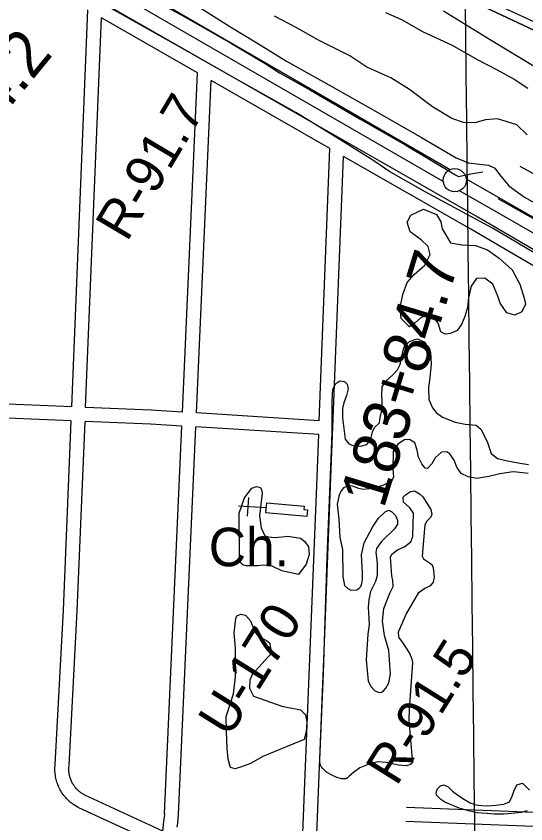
# Model space of a CAD drawing. Extents: x 3677843 to 3715951, y 511991 to 537744.
# Drawn here: x 3696854 to 3697951, y 526105 to 527844 of the extents above; entities that cross this region are included whole.
import ezdxf

# ---------------------------------------------------------------- set-up
doc = ezdxf.new("R2010")
doc.units = 0
for name, color, linetype in [('V-BLDG-OTLN', 7, 'Continuous'), ('V-FLOD-BASE', 7, 'Continuous'), ('V-GRID-MAJR', 7, 'Continuous'), ('V-LEVE-TOET', 7, 'Continuous'), ('V-RIVR-EDGE', 7, 'Continuous'), ('V-RIVR-RANG-IDEN', 7, 'Continuous'), ('V-ROAD-CNTR', 7, 'Continuous'), ('V-RRAP-FSHR', 7, 'Continuous'), ('V-SITE-OTLN', 7, 'Continuous'), ('V-SITE-OTLN-IDEN', 7, 'Continuous'), ('V-SITE-VEGE', 7, 'Continuous'), ('V-SURV-IDEN', 7, 'Continuous'), ('V-SURV-LINE', 7, 'Continuous'), ('V-TOPO-DPTH', 7, 'Continuous'), ('V-TOPO-MINR', 7, 'Continuous'), ('V-TOPO-WATR', 7, 'Continuous')]:
    doc.layers.add(name, color=color, linetype=linetype)

msp = doc.modelspace()

# ---------------------------------------------------------------- linework, layer by layer
at = {"layer": 'V-BLDG-OTLN'}
msp.add_lwpolyline([(3697391.767, 526774.828), (3697393.702, 526796.174), (3697474.295, 526788.865), (3697473.6520000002, 526781.783), (3697481.125, 526781.103), (3697479.8310000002, 526766.837)], close=True, dxfattribs=at)
at = {"layer": 'V-FLOD-BASE'}
for points in [[(3696963.823, 528025.251), (3696995.319, 527977.979), (3697007.7260000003, 527960.311), (3697020.612, 527949.805), (3697093.644, 527909.203), (3697209.634, 527846.628), (3697317.511, 527785.012), (3697390.063, 527742.025), (3697421.088, 527721.965), (3697487.437, 527684.707), (3697596.268, 527621.18), (3697692.688, 527566.251), (3697799.608, 527502.247), (3697806.29, 527498.425), (3697832.5500000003, 527504.147), (3697858.807, 527508.436)], [(3697891.256, 527451.6140000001), (3698032.066, 527371.3690000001), (3698147.577, 527303.067), (3698260.705, 527239.5380000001), (3698358.079, 527181.2660000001), (3698376.693, 527172.6680000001), (3698394.8340000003, 527169.797)]]:
    msp.add_lwpolyline(points, dxfattribs=at)
at = {"layer": 'V-GRID-MAJR'}
msp.add_spline([(3697869.728154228, 523644.39091797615), (3697800.0870000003, 529704.966), (3697730.4450000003, 535765.552), (3697730.4050000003, 535769.005)], degree=3, dxfattribs=at)
at = {"layer": 'V-LEVE-TOET'}
for points in [[(3698472.529, 527041.836), (3698361.237, 527107.313), (3698311.46, 527134.176), (3698275.108, 527154.884), (3698248.265, 527171.1140000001), (3698233.724, 527180.627), (3698164.377, 527221.48), (3698039.1010000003, 527292.554), (3697879.1520000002, 527387.692), (3697734.301, 527465.487), (3697656.563, 527510.259), (3697628.041, 527529.285), (3697610.704, 527541.036), (3697553.1, 527576.851), (3697456.349, 527636.172), (3697315.413, 527715.083), (3697199.646, 527781.68), (3697055.356, 527862.2710000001), (3697004.461, 527890.255), (3696967.552, 527915.435), (3696950.218, 527936.136)], [(3697236.031, 527871.167), (3697314.328, 527821.362), (3697371.93, 527786.106), (3697436.245, 527746.932), (3697533.556, 527692.086), (3697627.514, 527639.477), (3697726.504, 527582.954), (3697801.4450000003, 527538.742), (3697827.733, 527528.107), (3697851.7830000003, 527525.303), (3697870.8000000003, 527523.061), (3697884.782, 527516.902), (3697894.848, 527502.917), (3697914.419, 527478.3), (3697948.532, 527454.238), (3698041.929, 527401.0700000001)]]:
    msp.add_lwpolyline(points, dxfattribs=at)
at = {"layer": 'V-RIVR-EDGE'}
msp.add_lwpolyline([(3697774.287742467, 527855.332599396), (3697876.7871042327, 527792.0448515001), (3698092.5827345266, 527661.8406982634)], dxfattribs=at)
at = {"layer": 'V-ROAD-CNTR'}
for points in [[(3697847.86726536, 527411.081151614), (3697000.5939599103, 527896.364181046), (3696969.710021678, 527916.9121399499), (3696954.7250516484, 527929.4341149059), (3696929.2361026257, 527958.6060565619), (3696908.0561449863, 527985.235003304)], [(3696973.8140134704, 527002.59896858), (3697008.712943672, 527857.1412594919)], [(3697003.78895352, 527001.3769710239), (3697038.051884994, 527840.3372930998)], [(3697244.6574717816, 527722.0025297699), (3697038.051884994, 527840.3372930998)], [(3697212.247536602, 526991.3829910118), (3697244.655471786, 527722.0025297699)], [(3697242.192476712, 526989.4979947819), (3697273.941413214, 527705.228563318)], [(3697529.4889021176, 527558.86285605), (3697273.941413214, 527705.2295633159)], [(3697506.5909479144, 526972.8560280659), (3697529.48790212, 527558.861856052)], [(3697418.4121242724, 524147.15067948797), (3697430.934099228, 524455.6500624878), (3697472.191016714, 525398.1691774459), (3697491.9039772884, 525848.1442774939), (3697505.15795078, 526174.039625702), (3697518.02292505, 526495.2079833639), (3697530.41290027, 526814.1413454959), (3697558.853843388, 527542.0428896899)], [(3697832.9572951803, 527385.0492036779), (3697558.853843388, 527542.043889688)], [(3700025.079910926, 525999.309975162), (3699637.8166854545, 526223.06552765), (3699515.020931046, 526299.84537409), (3699487.6339858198, 526318.9453358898), (3699465.044031, 526340.9852918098), (3699441.2280786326, 526369.2072353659), (3699126.022709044, 526649.688674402), (3698935.528090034, 526775.5434226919), (3698552.726855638, 526999.5039747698), (3697847.976265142, 527411.0181517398)], [(3698024.977911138, 527272.9244279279), (3697832.848295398, 527385.112203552)], [(3696973.8140134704, 527002.59896858), (3696767.0014270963, 527011.025951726)], [(3697212.247536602, 526991.3839910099), (3697144.6486718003, 526995.6389824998), (3697003.78895352, 527001.3779710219)], [(3696972.590015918, 526972.6240285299), (3696765.773429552, 526981.0510116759)], [(3697506.5919479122, 526972.857028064), (3697242.1934767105, 526989.4989947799)], [(3696938.233084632, 526232.489508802), (3696955.9440492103, 526565.0548436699), (3696972.58901592, 526972.6240285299)], [(3696968.1910247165, 526230.8935119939), (3696985.911989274, 526563.6448464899), (3697002.56395597, 526971.4020309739)], [(3697210.9175392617, 526961.408050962), (3697143.094674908, 526965.677042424), (3697002.564955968, 526971.403030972)], [(3697173.8776133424, 526126.383721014), (3697210.9175392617, 526961.408050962)], [(3697203.847553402, 526125.0537236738), (3697240.8634793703, 526959.5230547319)], [(3697505.4199502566, 526942.8720880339), (3697240.8634793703, 526959.5230547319)], [(3697388.374184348, 524146.80568017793), (3697400.960159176, 524456.9140599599), (3697442.219076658, 525399.4811748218), (3697461.9300372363, 525849.410274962), (3697475.182010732, 526175.249623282), (3697488.0469850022, 526496.389981), (3697500.434960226, 526815.3093431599), (3697505.4199502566, 526942.8710880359)], [(3696988.8419834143, 526139.962693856), (3696986.414988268, 526141.222691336), (3696983.817993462, 526142.6786884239), (3696981.2699985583, 526144.218685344), (3696978.7760035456, 526145.8356821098), (3696976.331008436, 526147.5346787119), (3696973.9440132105, 526149.3096751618), (3696971.615017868, 526151.16067146), (3696969.3450224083, 526153.0856676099), (3696967.137026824, 526155.084663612), (3696964.998031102, 526157.1496594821), (3696962.92403525, 526159.2836552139), (3696960.920039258, 526161.482650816), (3696958.987043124, 526163.7456462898), (3696957.1280468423, 526166.0696416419), (3696955.34405041, 526168.4516368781), (3696953.6380538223, 526170.8906319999), (3696952.011057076, 526173.3796270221), (3696950.4650601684, 526175.921621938), (3696949.000063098, 526178.5116167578), (3696947.61906586, 526181.1496114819), (3696946.323068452, 526183.8286061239), (3696945.116070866, 526186.546600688), (3696943.9950731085, 526189.3015951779), (3696942.9610751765, 526192.097589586), (3696942.021077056, 526194.917583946), (3696941.170078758, 526197.7675782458), (3696940.411080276, 526200.64557249), (3696939.74408161, 526203.5455666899), (3696939.171082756, 526206.466560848), (3696938.692083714, 526209.4005549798), (3696938.307084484, 526212.3525490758), (3696938.017085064, 526215.3165431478), (3696937.822085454, 526218.2865372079), (3696937.7230856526, 526221.257531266), (3696937.71908566, 526224.234525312), (3696937.810085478, 526227.2085193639), (3696937.996085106, 526230.176513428), (3696938.2680845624, 526233.037507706), (3696938.3080844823, 526233.3865070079)], [(3697002.6699557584, 526166.5846406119), (3697000.66895976, 526167.6246385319), (3696998.9139632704, 526168.608636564), (3696997.191966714, 526169.6486344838), (3696995.499970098, 526170.7456322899), (3696993.846973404, 526171.894629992), (3696992.231976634, 526173.09562759), (3696990.6549797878, 526174.3486250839), (3696989.1189828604, 526175.651622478), (3696987.62898584, 526177.0006197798), (3696986.177988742, 526178.401616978), (3696984.77399155, 526179.84561409), (3696983.4179942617, 526181.3346111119), (3696982.110996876, 526182.8636080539), (3696980.8539993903, 526184.4356049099), (3696979.6460018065, 526186.047601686), (3696978.492004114, 526187.696598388), (3696977.391006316, 526189.3835950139), (3696976.3430084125, 526191.1055915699), (3696975.352010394, 526192.8575880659), (3696974.4190122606, 526194.639584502), (3696973.5430140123, 526196.4525808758), (3696972.72401565, 526198.2945771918), (3696971.9650171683, 526200.159573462), (3696971.2690185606, 526202.0435696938), (3696970.6310198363, 526203.9575658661), (3696970.0540209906, 526205.887562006), (3696969.541022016, 526207.8335581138), (3696969.090022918, 526209.79555419), (3696968.703023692, 526211.7705502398), (3696968.378024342, 526213.7605462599), (3696968.117024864, 526215.7565422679), (3696967.921025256, 526217.7585382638), (3696967.7900255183, 526219.7665342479), (3696967.723025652, 526221.7815302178), (3696967.7190256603, 526223.794526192), (3696967.782025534, 526225.806522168), (3696967.908025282, 526227.8185181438), (3696968.1080248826, 526229.9235139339), (3696968.1160248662, 526229.996513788)], [(3697170.1076208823, 526089.4747948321), (3697002.031957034, 526166.8976399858)], [(3697165.8526293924, 526058.4058569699), (3696989.479982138, 526139.6496944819)], [(3697694.130572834, 526140.8646920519), (3697968.286024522, 526130.222713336)], [(3697170.1076208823, 526089.4747948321), (3697172.3246164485, 526110.2007533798), (3697173.2266146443, 526119.367735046), (3697173.92361325, 526127.0697196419)], [(3697201.1615587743, 526097.7287783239), (3697202.16855676, 526107.1367595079), (3697203.094554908, 526116.547740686), (3697203.801553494, 526124.3677250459)], [(3697692.966575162, 526110.886752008), (3697966.9930271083, 526100.2507732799)]]:
    msp.add_lwpolyline(points, dxfattribs=at)
at = {"layer": 'V-RRAP-FSHR'}
msp.add_lwpolyline([(3697938.220454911, 527521.049574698), (3698516.60432745, 527203.8594304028), (3699111.751080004, 526846.0041980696), (3699438.6651283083, 526626.4114938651), (3699664.989608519, 526398.686181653), (3700251.7538970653, 526032.6983413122), (3700696.02039348, 525748.040677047), (3701056.4622498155, 525536.58262885)], dxfattribs=at)
at = {"layer": 'V-SITE-OTLN'}
for p, q in [((3697354.0750957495, 526807.5817980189), (3697351.6680134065, 526767.6537777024)), ((3697392.7985759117, 526785.2107505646), (3697332.907544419, 526788.821329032))]:
    msp.add_line(p, q, dxfattribs=at)
at = {"layer": 'V-SITE-VEGE'}
for points in [[(3697954.299, 527588.5), (3697931.718, 527609.963), (3697890.504, 527622.962), (3697864.531, 527620.711), (3697841.381, 527614.508), (3697817.102, 527615.079), (3697792.259, 527623.554), (3697750.484, 527648.411), (3697700.808, 527685.6900000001), (3697660.727, 527711.112), (3697609.353, 527733.712), (3697572.659, 527758.566), (3697504.913, 527791.9), (3697455.798, 527820.1460000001), (3697410.6350000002, 527843.8740000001)], [(3697648.912, 527851.707), (3697683.347, 527837.017), (3697730.205, 527810.4670000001), (3697792.872, 527781.086), (3697846.501, 527750.581), (3697889.406, 527727.984), (3697926.102, 527708.21), (3697955.4560000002, 527689.004)], [(3697699.651, 526329.148), (3697706.069, 526251.64), (3697707.913, 526239.901), (3697705.596, 526235.184), (3697703.264, 526232.819), (3697693.296, 526229.81), (3697676.832, 526231.459), (3697650.941, 526237.152), (3697632.716, 526238.789), (3697615.126, 526233.966), (3697594.032, 526225.591), (3697580.003, 526215.507), (3697571.2430000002, 526207.806), (3697567.475, 526203.762), (3697563.484, 526201.73), (3697555.472, 526201.675), (3697544.236, 526204.8), (3697532.577, 526210.328), (3697522.12, 526216.263), (3697514.055, 526223.818), (3697510.42, 526228.6), (3697509.197, 526231.395), (3697507.958, 526236.593), (3697507.921, 526243.4230000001), (3697515.64, 526429.507), (3697523.8850000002, 526679.264), (3697532.389, 526890.655), (3697534.1210000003, 526947.685), (3697534.734, 527012.699), (3697535.149, 527029.22), (3697536.1350000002, 527040.953), (3697542.444, 527052.7170000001), (3697550.931, 527058.64), (3697561.063, 527057.645), (3697566.433, 527051.8200000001), (3697568.634, 527041.711), (3697565.003, 527027.297), (3697559.789, 527011.276), (3697556.676, 526998.998), (3697556.8170000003, 526978.7490000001), (3697562.4620000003, 526933.497), (3697570.5270000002, 526923.427), (3697581.748, 526918.71), (3697595.606, 526918.274), (3697608.904, 526921.563), (3697617.883, 526933.349), (3697620.971, 526948.824), (3697625.169, 526958.446), (3697635.94, 526968.434), (3697637.805, 526979.851), (3697641.9420000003, 526997.9940000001), (3697641.83, 527013.979), (3697641.201, 527027.832), (3697642.139, 527045.955), (3697648.99, 527057.194), (3697665.4020000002, 527072.228), (3697674.923, 527082.419), (3697680.703, 527094.183), (3697684.815, 527115.525), (3697689.497, 527132.077), (3697700.6070000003, 527143.345), (3697717.086, 527149.321), (3697733.654, 527141.977), (3697746.065, 527120.213), (3697747.304, 527095.18), (3697744.312, 527065.853), (3697741.805, 527043.454), (3697742.514, 527018.4130000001), (3697750.097, 527000.35), (3697758.16, 526990.282), (3697772.0870000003, 526980.255), (3697799.335, 526969.787), (3697820.68, 526965.6730000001), (3697844.144, 526963.172), (3697855.395, 526954.192), (3697868.382, 526926.04), (3697876.541, 526902.1190000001), (3697890.469, 526891.56), (3697911.822, 526886.378), (3697934.7630000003, 526882.274), (3697957.169, 526878.703)], [(3697739.8200000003, 526869.724), (3697734.483, 526870.752), (3697727.489, 526880.296), (3697720.463, 526894.634), (3697717.161, 526909.531), (3697712.258, 526924.948), (3697701.017, 526932.331), (3697690.363, 526931.725), (3697676.04, 526922.567), (3697666.0270000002, 526906.51), (3697665.2260000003, 526868.671), (3697666.4080000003, 526852.16), (3697664.313, 526846.817), (3697661.147, 526842.531), (3697643.091, 526833.348), (3697621.823, 526826.804), (3697600.915, 526825.125)], [(3697956.235, 526859.513), (3697945.034, 526861.032), (3697923.71, 526862.482), (3697894.963, 526858.552), (3697871.556, 526853.06), (3697846.009, 526848.6190000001), (3697827.3340000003, 526852.216), (3697811.832, 526859.0380000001), (3697802.6780000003, 526872.829), (3697796.7120000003, 526887.706), (3697787.555, 526901.497), (3697781.133, 526905.714), (3697769.949, 526905.103), (3697756.176, 526893.284), (3697748.807, 526879.9130000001), (3697739.8200000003, 526869.724)], [(3697600.915, 526825.125), (3697591.592, 526827.208), (3697575.694, 526832.385), (3697565.126, 526831.136), (3697558.683, 526828.154), (3697552.279, 526819.884), (3697548.824, 526809.873), (3697545.414, 526793.395), (3697548.576, 526761.104), (3697550.614, 526721.754), (3697556.6720000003, 526695.9450000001), (3697557.075, 526637.782), (3697560.737, 526618.4180000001), (3697568.423, 526611.422), (3697574.326, 526607.939), (3697587.244, 526608.616), (3697592.508, 526612.178), (3697596.008, 526615.727), (3697598.312, 526622.207), (3697600.014, 526631.032), (3697599.324, 526645.716), (3697597.878, 526684.483), (3697603.575, 526709.786), (3697621.551, 526743.987), (3697633.755, 526762.876), (3697648.3510000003, 526776.4890000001), (3697656.551, 526780.073), (3697663.037, 526776.593), (3697670.727, 526769.008), (3697674.911, 526759.0480000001), (3697674.973, 526750.236), (3697668.579, 526740.205), (3697640.568, 526712.98), (3697629.511, 526697.629), (3697628.395, 526689.3960000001), (3697630.9, 526667.087), (3697631.092, 526639.474), (3697627.66, 526626.524), (3697616.643, 526605.297), (3697613.2460000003, 526587.059), (3697611.593, 526571.183), (3697614.202, 526534.188), (3697610.821, 526513.599), (3697607.681, 526458.351), (3697612.119, 526411.965), (3697618.079, 526399.669), (3697625.184, 526392.081), (3697634.613, 526388.035), (3697640.4820000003, 526388.6630000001), (3697644.574, 526391.629), (3697649.825, 526396.954), (3697656.207, 526408.748), (3697660.184, 526428.165), (3697656.309, 526478.079), (3697646.684, 526510.327), (3697642.94, 526541.4400000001), (3697645.69, 526568.484), (3697658.386, 526601.475), (3697665.335, 526615.625), (3697664.659, 526628.546), (3697662.824, 526639.107), (3697660.194, 526679.041), (3697663.086, 526685.525), (3697674.77, 526695.007), (3697690.5840000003, 526702.167), (3697704.026, 526712.2490000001), (3697708.06, 526723.442), (3697709.469, 526773.978), (3697701.75, 526785.674), (3697687.5700000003, 526797.327), (3697686.9020000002, 526808.485), (3697692.157, 526813.2220000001), (3697702.684, 526820.3470000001), (3697711.488, 526821.584), (3697722.103, 526815.782), (3697729.791, 526808.786), (3697747.017, 526781.879), (3697748.8540000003, 526771.316), (3697745.967, 526764.248), (3697738.381, 526756.556), (3697733.736, 526748.884), (3697728.3310000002, 526681.279), (3697730.723, 526675.422), (3697743.71, 526666.7), (3697749.614, 526662.628), (3697752.008, 526656.181), (3697753.911, 526636.219), (3697751.6350000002, 526625.039), (3697745.2290000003, 526617.357), (3697733.521, 526611.4), (3697719.486, 526601.901), (3697694.5270000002, 526558.25), (3697676.597, 526517.585), (3697677.25, 526508.189), (3697678.45, 526504.672), (3697685.5670000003, 526495.321), (3697701.597, 526471.345), (3697705.791, 526459.622), (3697707.603, 526452.585), (3697700.083, 526351.478), (3697699.651, 526329.148)], [(3697954.267, 526132.979), (3697940.973, 526129.155), (3697920.737, 526127.416), (3697903.6950000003, 526125.7), (3697883.977, 526126.093), (3697867.98, 526127.58), (3697846.656, 526129.03), (3697827.444, 526133.159), (3697807.687, 526138.883), (3697776.693, 526151.456), (3697768.126, 526157.258), (3697759.004, 526166.785), (3697757.898, 526172.106), (3697761.04, 526180.12), (3697767.387, 526187.093), (3697774.833, 526188.7440000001), (3697783.9220000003, 526184.5430000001), (3697793.58, 526175.02), (3697806.968, 526165.5210000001), (3697819.2830000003, 526157.082), (3697831.5870000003, 526150.2390000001), (3697843.341, 526146.059), (3697856.139, 526144.55), (3697868.93, 526144.105), (3697886.506, 526145.295), (3697903.548, 526147.012), (3697915.764, 526152.426), (3697921.542, 526164.723), (3697925.722, 526176.474), (3697932.029, 526188.774), (3697944.2600000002, 526192.5920000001), (3697958.754, 526177.238)]]:
    msp.add_lwpolyline(points, dxfattribs=at)
for points in [[(3697768.48, 527164.56), (3697762.279, 527182.616), (3697752.129, 527195.596), (3697737.4590000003, 527198.42), (3697725.611, 527195.039), (3697713.7600000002, 527184.324), (3697700.781, 527175.3), (3697682.7320000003, 527192.794), (3697680.484, 527216.491), (3697686.132, 527244.699), (3697695.731, 527270.649), (3697710.97, 527287.569), (3697734.1070000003, 527307.871), (3697745.397, 527330.9990000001), (3697740.89, 527347.926), (3697726.224, 527362.6), (3697702.535, 527379.533), (3697695.77, 527400.41), (3697703.673, 527415.639), (3697730.756, 527428.044), (3697758.963, 527416.7490000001), (3697768.5500000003, 527400.953), (3697770.8030000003, 527386.283), (3697788.845, 527355.813), (3697814.2320000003, 527351.854), (3697843.009, 527350.154), (3697868.392, 527341.12), (3697893.775, 527323.057), (3697921.9760000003, 527297.662), (3697938.329, 527267.192), (3697947.346, 527236.7220000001), (3697950.162, 527223.746), (3697942.259, 527207.386), (3697927.589, 527200.056), (3697910.1010000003, 527205.139), (3697896.003, 527226.017), (3697890.93, 527241.254), (3697880.217, 527267.208), (3697863.296, 527279.625), (3697845.241, 527279.066), (3697833.389, 527262.709), (3697827.741, 527237.322), (3697825.4760000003, 527216.448), (3697819.83, 527197.269), (3697813.055, 527179.779), (3697803.46, 527167.37), (3697788.788, 527160.606), (3697777.506, 527158.916)], [(3697461.753, 526641.669), (3697426.3310000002, 526649.957), (3697405.536, 526659.569), (3697387.2290000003, 526661.879), (3697373.822, 526660.566), (3697349.437, 526660.3960000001), (3697342.103, 526662.784), (3697338.429, 526665.197), (3697334.71, 526673.706), (3697334.011, 526773.693), (3697345.9760000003, 526806.701), (3697361.682, 526827.541), (3697371.412, 526831.267), (3697379.964, 526828.887), (3697382.436, 526824.027), (3697383.7060000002, 526816.72), (3697377.951, 526767.904), (3697381.787, 526742.322), (3697389.223, 526725.303), (3697396.557, 526722.9130000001), (3697412.417, 526721.805), (3697439.225, 526724.433), (3697466.0870000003, 526719.743), (3697475.8910000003, 526712.493), (3697483.284, 526701.571), (3697484.625, 526684.509), (3697478.6720000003, 526663.736)], [(3697473.988, 526286.906), (3697385.23, 526249.702), (3697358.505, 526234.883), (3697339.0470000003, 526227.43), (3697325.66, 526223.678), (3697315.889, 526226.05), (3697310.883, 526244.306), (3697308.282, 526267.456), (3697306.808, 526304.03), (3697306.5870000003, 526335.733), (3697310.166, 526346.733), (3697314.934, 526362.6190000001), (3697322.096, 526384.616), (3697326.718, 526421.233), (3697326.284, 526483.4180000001), (3697323.616, 526516.323), (3697327.06, 526546.834), (3697329.457, 526552.948), (3697337.968, 526556.667), (3697347.739, 526554.295), (3697358.798, 526542.177), (3697363.769, 526528.8), (3697367.494, 526519.0700000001), (3697374.879, 526509.366), (3697393.237, 526499.737), (3697400.598, 526493.693), (3697400.647, 526486.379), (3697404.399, 526472.988), (3697362.046, 526426.357), (3697357.254, 526414.128), (3697356.154, 526397.05), (3697364.807, 526380.037), (3697391.701, 526370.471), (3697425.93, 526358.515), (3697466.228, 526350.261), (3697477.2770000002, 526339.362), (3697479.829, 526323.527), (3697478.754, 526302.791)]]:
    msp.add_lwpolyline(points, close=True, dxfattribs=at)
at = {"layer": 'V-SURV-LINE'}
for points in [[(3697026.4984274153, 527954.7999564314), (3697788.5065170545, 527513.6011783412)], [(3697773.47298206, 527487.6398064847), (3697011.4641852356, 527928.8389940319)], [(3697823.0585507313, 527493.7099047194), (3699005.265645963, 526817.0200792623)], [(3698990.363695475, 526790.9829543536), (3697808.155596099, 527467.6733545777)]]:
    msp.add_lwpolyline(points, dxfattribs=at)
msp.add_circle((3697798.274, 527490.61347), 25, dxfattribs=at)
at = {"layer": 'V-TOPO-DPTH'}
msp.add_lwpolyline([(3700135.6219622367, 526219.5749361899), (3700041.3816211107, 526283.1822090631), (3699947.1849957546, 526346.8540836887), (3699853.053944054, 526410.6228609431), (3699758.966608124, 526474.4562399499), (3699381.262740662, 526730.9926294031), (3699361.5524011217, 526744.5234377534), (3699341.9331696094, 526758.18372153), (3699322.450600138, 526772.0382184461), (3699303.0591386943, 526786.0221907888), (3698511.850577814, 527539.7586940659), (3698506.379409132, 527543.5127771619), (3698500.85876137, 527547.1909203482), (3698495.263894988, 527550.7551536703), (3698489.619549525, 527554.2434470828), (3698409.0221530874, 527602.9194881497), (3698380.503073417, 527619.4890325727), (3698351.6350704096, 527635.3992479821), (3698322.243682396, 527650.3204698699), (3698292.503371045, 527664.5823627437), (3698262.2863579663, 527677.7966989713), (3698231.784444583, 527690.2775630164), (3697406.8024188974, 528077.5424758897)], dxfattribs=at)
at = {"layer": 'V-TOPO-MINR'}
msp.add_lwpolyline([(3697426.2658131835, 528083.242409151), (3698136.965833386, 527754.4388219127), (3698185.4520927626, 527732.5851930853), (3698233.2521856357, 527709.2854298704), (3698280.5234551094, 527684.9954248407), (3698327.0014894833, 527659.2200570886), (3698372.9507004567, 527632.4544475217), (3698487.4844717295, 527563.2840725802), (3698495.9507174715, 527558.0518673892), (3698504.342731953, 527552.7057327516), (3698512.623399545, 527547.1887039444), (3698520.8298358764, 527541.5577456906), (3698638.352014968, 527459.1337250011), (3699332.9797798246, 526791.1026917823), (3699343.557215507, 526783.473824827), (3699354.1837664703, 526775.9147262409), (3699364.8839903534, 526768.4602802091), (3699375.633329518, 526761.0756025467), (3699520.1542458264, 526662.831731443), (3699603.224557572, 526606.412380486), (3699686.3264289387, 526550.0395952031), (3699769.475639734, 526493.7366584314), (3699852.656410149, 526437.4802873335), (3700292.0971918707, 526140.5490601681)], dxfattribs=at)
at = {"layer": 'V-TOPO-WATR'}
msp.add_lwpolyline([(3697406.8024188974, 528077.5424758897), (3698231.784444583, 527690.2775630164), (3698262.2863579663, 527677.7966989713), (3698292.503371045, 527664.5823627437), (3698322.243682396, 527650.3204698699), (3698351.6350704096, 527635.3992479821), (3698380.503073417, 527619.4890325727), (3698409.0221530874, 527602.9194881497), (3698489.619549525, 527554.2434470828), (3698495.263894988, 527550.7551536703), (3698500.85876137, 527547.1909203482), (3698506.379409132, 527543.5127771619), (3698511.850577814, 527539.7586940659), (3699303.0591386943, 526786.0221907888), (3699322.450600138, 526772.0382184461), (3699341.9331696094, 526758.18372153), (3699361.5524011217, 526744.5234377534), (3699381.262740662, 526730.9926294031), (3699758.966608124, 526474.4562399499), (3699853.053944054, 526410.6228609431), (3699947.1849957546, 526346.8540836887), (3700041.3816211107, 526283.1822090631), (3700135.6219622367, 526219.5749361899)], dxfattribs=at)

# ---------------------------------------------------------------- texts
at = {"layer": 'V-RIVR-RANG-IDEN'}
for s, height, rotation, p in [('R-91.7', 82.99999799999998, 59.284705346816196, (3697092.6210000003, 527355.895)), ('U-170', 83, 58.03532571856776, (3697312.267373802, 526288.4181280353)), ('R-91.5', 82.99999800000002, 58.00345882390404, (3697672.913, 526183.96))]:
    msp.add_text(s, height=height, rotation=rotation, dxfattribs=at).set_placement(p)
at = {"layer": 'V-SITE-OTLN-IDEN'}
msp.add_text('Ch.', height=82.99983200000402, dxfattribs=at).set_placement((3697268.7804235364, 526659.5396546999))
at = {"layer": 'V-SURV-IDEN'}
for s, height, rotation, p in [('174+64.2', 100.00000000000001, 50.67840514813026, (3696579.671530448, 527327.6395784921)), ('183+84.7', 99.99999999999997, 73.05125009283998, (3697645.3586599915, 526781.473511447))]:
    msp.add_text(s, height=height, rotation=rotation, dxfattribs=at).set_placement(p)

doc.saveas('drawing.dxf')
